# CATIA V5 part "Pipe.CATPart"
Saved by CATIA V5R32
Part number: Pipe
Bounding box of the stored display mesh (mm): x -50 to 50, y 0 to 150, z -50 to 50
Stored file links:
  D:\PROJECTS\Project 2022\CATIA V5 6R 2022\Resources\Part Files\c12_catia_v5_6r2022_prt\c12_catia_v5-6r2022 figr_12-39\Pipe.CATPart
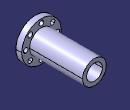
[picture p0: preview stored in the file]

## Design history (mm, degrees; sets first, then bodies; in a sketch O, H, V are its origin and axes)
Body1 (main body)
  Sketch1 on zx-plane, origin (0, 0, 0), H (-1, 0, 0), V (0, 0, 1)
    circle A1 centre (0, 0) radius 50
    point P1 (0, -50)
    circle A2 centre (0, 0) radius 30
    point P2 (0, -30)
    radius A1 = 50
    radius A2 = 30
    coincidence: A1 P1, P1 V, A2 P2, P2 V
  MultiPad1: profile Sketch1, domains (length 150; length 15)
  Sketch2 on face of MultiPad1, origin (0, 150, 0), H (-1, 0, 0), V (0, 0, 1)
    circle A1 centre (0, 0) radius 20
    point P1 (0, -20)
    radius A1 = 20
    coincidence: A1 P1, P1 V
  Pocket1: profile Sketch2, direction (0, -1, 0), through (limit type 3)
  Sketch3 on face of MultiPad1, origin (0, 0, 0), H (1, 0, 0), V (0, 0, 1)
    circle A1 centre (0, -40) radius 6
    point P1 (0, -40)
    radius A1 = 6
    distance H P1 = 40
    coincidence: P1 V
  Pocket2: profile Sketch3, direction (0, 1, 0), through (limit type 3)
  CircPattern1: of Pocket2, instances 8, angular step 45, axis from face of MultiPad1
